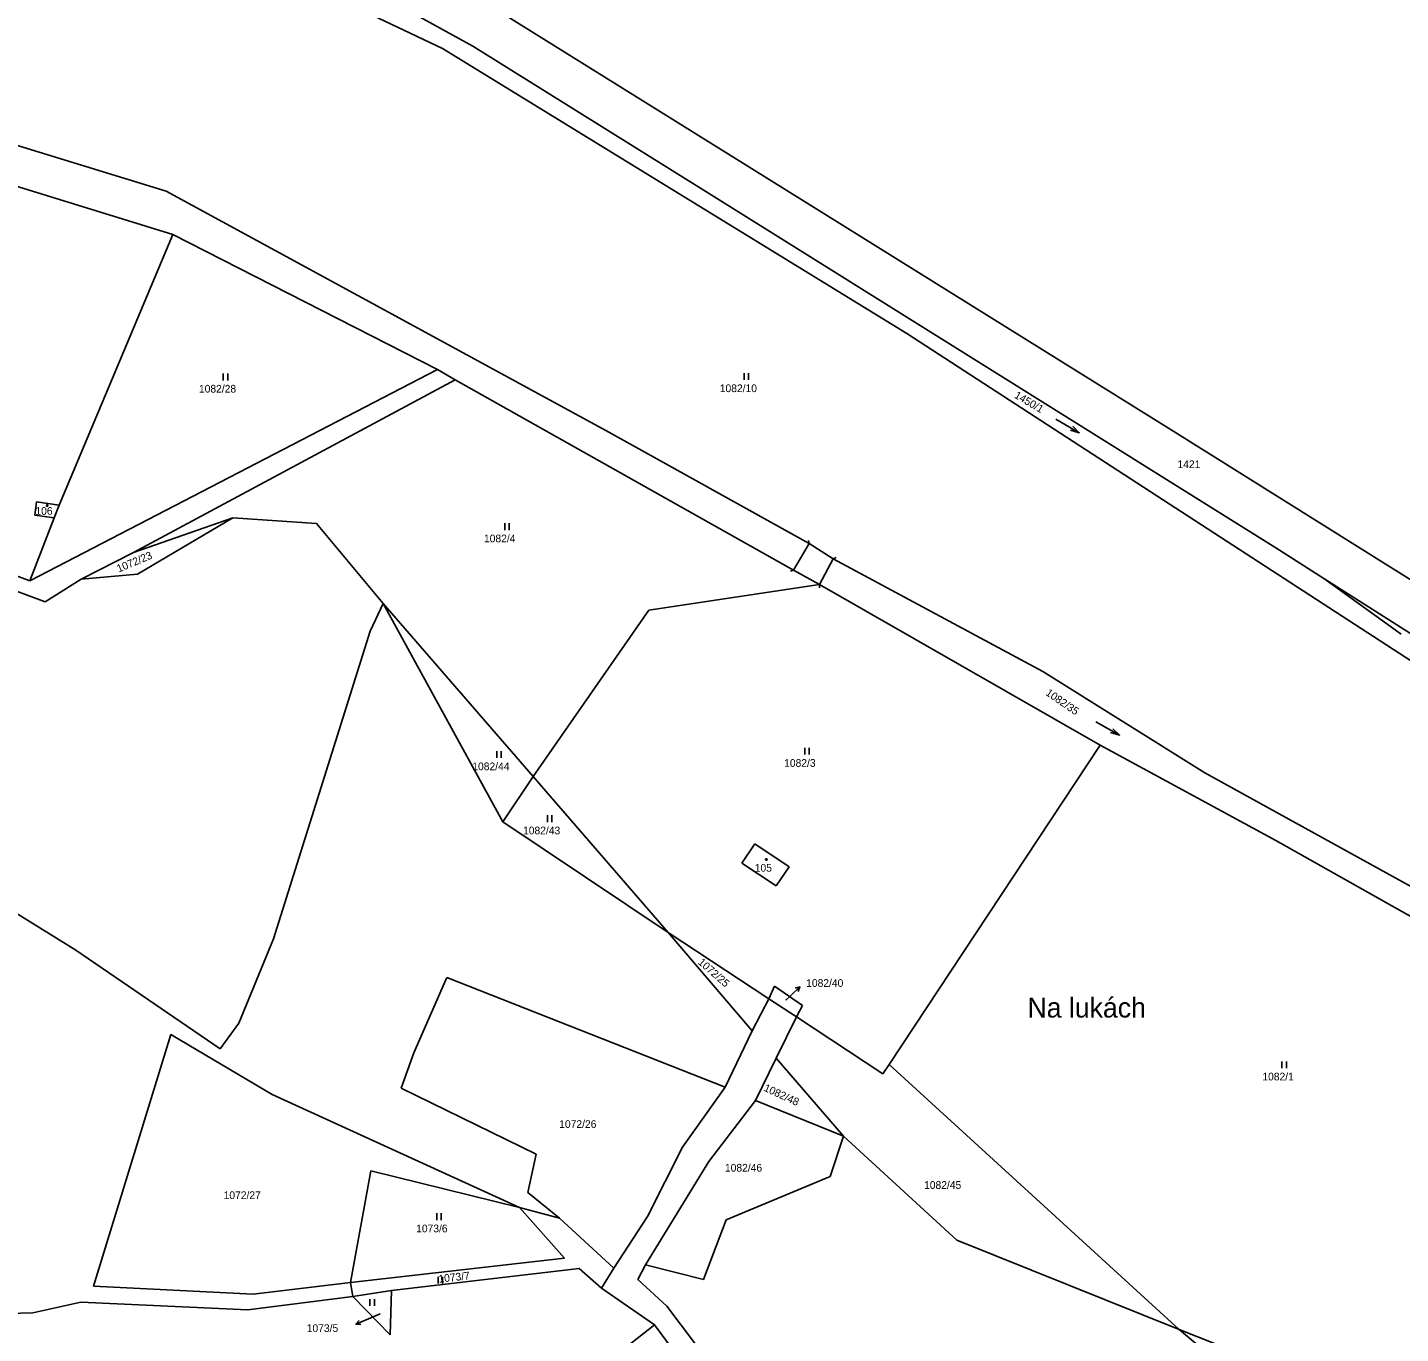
# Model space of a CAD drawing. Extents: x -850689 to -847910, y -1058374 to -1054747.
# Drawn here: x -849820.3 to -849516.8, y -1056154.2 to -1055865.6 of the extents above; entities that cross this region are included whole.
import ezdxf

# ---------------------------------------------------------------- set-up
doc = ezdxf.new("R2010")
doc.units = 0
for name, color, linetype in [('KN_HRANICE', 7, 'Continuous'), ('KN_KULTURY', 7, 'Continuous'), ('KN_PARCELY', 7, 'Continuous'), ('KN_SLUCKY', 7, 'Continuous'), ('KN_STAVEBNI', 7, 'Continuous')]:
    doc.layers.add(name, color=color, linetype=linetype)

# ---------------------------------------------------------------- blocks, each defined once
blk = doc.blocks.new('306')
for p, q in [((-0.5, 1.5), (-0.5, 0)), ((0.5, 0), (0.5, 1.5))]:
    blk.add_line(p, q)
blk = doc.blocks.new('802')
blk.add_line((-3, 0), (3, 0))
blk.add_lwpolyline([(1, 0.5), (3, 0), (1, -0.5)])
blk = doc.blocks.new('10292')
blk.add_line((0, 3), (0, 0))
blk.add_lwpolyline([(-0.5, 2), (0, 3), (0.5, 2)])
blk = doc.blocks.new('4201')
blk.add_line((0, 0), (-0.5, -0.5))
blk = doc.blocks.new('402')
blk.add_lwpolyline([(0.09, 0.15), (0.18, 0), (0.09, -0.15), (-0.09, -0.15), (-0.18, 0), (-0.09, 0.15), (0.09, 0.15)])

msp = doc.modelspace()

# ---------------------------------------------------------------- linework, layer by layer
at = {"layer": 'KN_HRANICE'}
for p, q in [((-849925.48, -1055776.91), (-849728.57, -1055870.26)), ((-849789.66, -1055901.84), (-849941.49, -1055855.07)), ((-849750.81, -1055853.82), (-849721.84, -1055869.75)), ((-849723.4, -1055857.46), (-849567.55, -1055954.51)), ((-849925.74, -1055868.85), (-849788.17, -1055911.4)), ((-849728.57, -1055870.26), (-849625.96, -1055933.24)), ((-849721.84, -1055869.75), (-849670.35, -1055901.85)), ((-849789.66, -1055901.84), (-849692.46, -1055954.72)), ((-849670.35, -1055901.85), (-849544.39, -1055980.59)), ((-849788.17, -1055911.4), (-849813.32, -1055971.18)), ((-849788.17, -1055911.4), (-849729.7, -1055941.2)), ((-849625.96, -1055933.24), (-849531.18, -1055994.73)), ((-849953.34, -1055938.37), (-849819.81, -1055987.92)), ((-849819.81, -1055987.92), (-849729.7, -1055941.2)), ((-849725.75, -1055943.47), (-849729.7, -1055941.2)), ((-849796.89, -1055981.61), (-849725.75, -1055943.47)), ((-849725.75, -1055943.47), (-849651, -1055985.57)), ((-849816.4, -1055992.51), (-849916.66, -1055955.41)), ((-849692.46, -1055954.72), (-849647.54, -1055979.67)), ((-849567.55, -1055954.51), (-849412.04, -1056051.96)), ((-849818.29, -1055970.47), (-849818.7, -1055973.39)), ((-849818.29, -1055970.47), (-849813.32, -1055971.18)), ((-849814.41, -1055974), (-849813.32, -1055971.18)), ((-849819.81, -1055987.92), (-849814.41, -1055974)), ((-849818.7, -1055973.39), (-849814.41, -1055974)), ((-849796.89, -1055981.61), (-849774.92, -1055974.01)), ((-849774.92, -1055974.01), (-849796, -1055986.42)), ((-849756.41, -1055975.27), (-849774.92, -1055974.01)), ((-849741.66, -1055992.91), (-849756.41, -1055975.27)), ((-849647.54, -1055979.67), (-849642.19, -1055983.02)), ((-849544.39, -1055980.59), (-849533.77, -1055987.36)), ((-849808.42, -1055987.54), (-849796.89, -1055981.61)), ((-849642.19, -1055983.02), (-849595.86, -1056007.92)), ((-849796, -1055986.42), (-849808.42, -1055987.54)), ((-849645.25, -1055988.73), (-849651, -1055985.57)), ((-849808.42, -1055987.54), (-849816.4, -1055992.51)), ((-849682.98, -1055994.38), (-849645.25, -1055988.73)), ((-849645.25, -1055988.73), (-849583.23, -1056024.23)), ((-849533.77, -1055987.36), (-849447.97, -1056042.09)), ((-849533.77, -1055987.36), (-849516.66, -1055999.69)), ((-849744.55, -1055999.02), (-849741.66, -1055992.91)), ((-849741.66, -1055992.91), (-849715.21, -1056041.18)), ((-849741.66, -1055992.91), (-849708.56, -1056031.12)), ((-849708.56, -1056031.12), (-849682.98, -1055994.38)), ((-849473.77, -1056032.19), (-849531.18, -1055994.73)), ((-849765.92, -1056066.99), (-849744.55, -1055999.02)), ((-849560.1, -1056030.34), (-849595.86, -1056007.92)), ((-849629.86, -1056094.78), (-849583.23, -1056024.23)), ((-849583.23, -1056024.23), (-849544.37, -1056045.31)), ((-849715.21, -1056041.18), (-849708.56, -1056031.12)), ((-849708.56, -1056031.12), (-849705.72, -1056034.36)), ((-849443.99, -1056094.41), (-849560.1, -1056030.34)), ((-849705.72, -1056034.36), (-849678.66, -1056065.64)), ((-849678.66, -1056065.64), (-849715.21, -1056041.18)), ((-849662.41, -1056050.28), (-849659.57, -1056046.02)), ((-849659.57, -1056046.02), (-849651.93, -1056051.1)), ((-849544.37, -1056045.31), (-849445.63, -1056100.85)), ((-849654.82, -1056055.3), (-849662.41, -1056050.28)), ((-849838.15, -1056051.85), (-849809.64, -1056069.48)), ((-849651.93, -1056051.1), (-849654.82, -1056055.3)), ((-849660.09, -1056087.3), (-849678.66, -1056065.64)), ((-849656.44, -1056080.25), (-849678.66, -1056065.64)), ((-849773.59, -1056085.64), (-849765.92, -1056066.99)), ((-849809.64, -1056069.48), (-849777.71, -1056091.31)), ((-849734.87, -1056092.19), (-849727.59, -1056075.54)), ((-849727.59, -1056075.54), (-849666.07, -1056099.8)), ((-849655.22, -1056077.44), (-849656.44, -1056080.25)), ((-849649.02, -1056081.72), (-849655.22, -1056077.44)), ((-849660.09, -1056087.3), (-849656.44, -1056080.25)), ((-849650.34, -1056084.27), (-849656.44, -1056080.25)), ((-849650.34, -1056084.27), (-849649.02, -1056081.72)), ((-849777.71, -1056091.31), (-849773.59, -1056085.64)), ((-849654.81, -1056093.4), (-849650.34, -1056084.27)), ((-849631.22, -1056096.84), (-849650.34, -1056084.27)), ((-849788.62, -1056088.16), (-849805.73, -1056143.74)), ((-849766.22, -1056101.38), (-849788.62, -1056088.16)), ((-849660.09, -1056087.3), (-849666.07, -1056099.8)), ((-849734.87, -1056092.19), (-849737.69, -1056099.99)), ((-849659.37, -1056102.71), (-849654.81, -1056093.4)), ((-849639.94, -1056110.6), (-849654.81, -1056093.4)), ((-849631.22, -1056096.84), (-849629.86, -1056094.78)), ((-849629.86, -1056094.78), (-849565.73, -1056153.32)), ((-849711.58, -1056126.38), (-849766.22, -1056101.38)), ((-849737.69, -1056099.99), (-849707.88, -1056114.62)), ((-849666.07, -1056099.8), (-849675.53, -1056113.02)), ((-849669.71, -1056116.18), (-849659.37, -1056102.71)), ((-849659.37, -1056102.71), (-849639.94, -1056110.6)), ((-849642.89, -1056119.55), (-849639.94, -1056110.6)), ((-849639.94, -1056110.6), (-849614.89, -1056133.59)), ((-849675.53, -1056113.02), (-849683.26, -1056128.33)), ((-849707.88, -1056114.62), (-849709.73, -1056123.05)), ((-849683.7, -1056139.02), (-849669.71, -1056116.18)), ((-849748.92, -1056142.97), (-849744.42, -1056118.28)), ((-849744.42, -1056118.28), (-849711.58, -1056126.38)), ((-849665.85, -1056129.09), (-849642.89, -1056119.55)), ((-849709.73, -1056123.05), (-849702.72, -1056128.75)), ((-849711.58, -1056126.38), (-849702.72, -1056128.75)), ((-849701.62, -1056137.6), (-849711.58, -1056126.38)), ((-849690.71, -1056139.77), (-849702.72, -1056128.75)), ((-849683.26, -1056128.33), (-849690.71, -1056139.77)), ((-849670.9, -1056142.31), (-849665.85, -1056129.09)), ((-849614.89, -1056133.59), (-849565.73, -1056153.32)), ((-849748.92, -1056142.97), (-849701.62, -1056137.6)), ((-849739.81, -1056144.71), (-849698.33, -1056139.88)), ((-849698.33, -1056139.88), (-849693.42, -1056144.17)), ((-849690.71, -1056139.77), (-849693.42, -1056144.17)), ((-849683.7, -1056139.02), (-849685.43, -1056142.27)), ((-849683.7, -1056139.02), (-849670.9, -1056142.31)), ((-849805.73, -1056143.74), (-849770.42, -1056145.53)), ((-849770.42, -1056145.53), (-849748.92, -1056142.97)), ((-849748.39, -1056146.04), (-849748.92, -1056142.97)), ((-849693.42, -1056144.17), (-849681.71, -1056152.3)), ((-849685.43, -1056142.27), (-849679.02, -1056148.18)), ((-849819.12, -1056149.64), (-849808.52, -1056147.27)), ((-849808.52, -1056147.27), (-849771.61, -1056149)), ((-849771.61, -1056149), (-849748.39, -1056146.04)), ((-849748.39, -1056146.04), (-849739.81, -1056144.71)), ((-849748.39, -1056146.04), (-849740.13, -1056154.54)), ((-849739.81, -1056144.71), (-849740.13, -1056154.54)), ((-849837.94, -1056150.19), (-849819.12, -1056149.64)), ((-849679.02, -1056148.18), (-849647.93, -1056189.13)), ((-849681.71, -1056152.3), (-849708.52, -1056173.28)), ((-849681.71, -1056152.3), (-849647.07, -1056198.84)), ((-849565.73, -1056153.32), (-849533.49, -1056180.31)), ((-849565.73, -1056153.32), (-849527.38, -1056168.45))]:
    msp.add_line(p, q, dxfattribs=at)
at = {"layer": 'KN_PARCELY'}
for p, q in [((-849652.7, -1056080.56), (-849651.76, -1056079.68)), ((-849742.32, -1056149.85), (-849744.95, -1056150.99))]:
    msp.add_line(p, q, dxfattribs=at)
at = {"layer": 'KN_SLUCKY'}
for p, q in [((-849651, -1055985.57), (-849647.54, -1055979.67)), ((-849642.19, -1055983.02), (-849645.25, -1055988.73))]:
    msp.add_line(p, q, dxfattribs=at)
at = {"layer": 'KN_STAVEBNI'}
for p, q in [((-849818.29, -1055970.47), (-849818.7, -1055973.39)), ((-849818.29, -1055970.47), (-849813.32, -1055971.18)), ((-849814.41, -1055974), (-849813.32, -1055971.18)), ((-849818.7, -1055973.39), (-849814.41, -1055974)), ((-849662.41, -1056050.28), (-849659.57, -1056046.02)), ((-849659.57, -1056046.02), (-849651.93, -1056051.1)), ((-849654.82, -1056055.3), (-849662.41, -1056050.28)), ((-849651.93, -1056051.1), (-849654.82, -1056055.3))]:
    msp.add_line(p, q, dxfattribs=at)

# ---------------------------------------------------------------- block references
at = {"layer": 'KN_KULTURY'}
for name, p in [('306', (-849776.53, -1055943.61)), ('306', (-849661.41, -1055943.51)), ('402', (-849815.94, -1055971.28)), ('306', (-849714.3, -1055976.7)), ('306', (-849716.07, -1056027.05)), ('306', (-849648, -1056026.3)), ('306', (-849704.89, -1056041.22)), ('402', (-849657, -1056049.47)), ('306', (-849542.54, -1056095.59)), ('306', (-849729.33, -1056129.15)), ('306', (-849729.06, -1056143.18)), ('306', (-849744.11, -1056148.11))]:
    msp.add_blockref(name, p, dxfattribs=at)
for p, rotation in [((-849590.4, -1055953.67), -30.434675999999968), ((-849581.52, -1056020.52), -29.346056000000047)]:
    msp.add_blockref('802', p, dxfattribs=dict(at, rotation=rotation))
at = {"layer": 'KN_PARCELY'}
for p, rotation in [((-849651.76, -1056079.68), -46.706677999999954), ((-849744.95, -1056150.99), 113.38834800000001)]:
    msp.add_blockref('10292', p, dxfattribs=dict(at, rotation=rotation))
at = {"layer": 'KN_SLUCKY'}
for p, rotation in [((-849647.54, -1055979.67), -124.22786700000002), ((-849642.19, -1055983.02), 155.27156200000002), ((-849651, -1055985.57), -27.799070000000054), ((-849645.25, -1055988.73), 47.670089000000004)]:
    msp.add_blockref('4201', p, dxfattribs=dict(at, rotation=rotation))

# ---------------------------------------------------------------- texts
at = {"layer": 'KN_PARCELY'}
for s, height, p in [('1082/28', 1.7, (-849782.4, -1055946.31)), ('1082/10', 1.7, (-849667.28, -1055946.21)), ('1421', 1.7, (-849566.12, -1055963)), ('106', 1.7, (-849818.54, -1055973.31)), ('1082/4', 1.7, (-849719.4, -1055979.4)), ('1082/44', 1.7, (-849721.98, -1056029.75)), ('1082/3', 1.7, (-849653.06, -1056029)), ('1082/43', 1.7, (-849710.76, -1056043.92)), ('105', 1.7, (-849659.55, -1056052.17)), ('1082/40', 1.7, (-849648.19, -1056077.62)), ('1082/40', 0.1, (-849653.05, -1056080.56)), ('Na lukách', 4.4, (-849599.27, -1056084.4)), ('1082/1', 1.7, (-849547.36, -1056098.29)), ('1072/26', 1.7, (-849702.77, -1056108.79)), ('1082/46', 1.7, (-849666.14, -1056118.44)), ('1072/27', 1.7, (-849776.94, -1056124.5)), ('1082/45', 1.7, (-849622.13, -1056122.25)), ('1073/6', 1.7, (-849734.39, -1056131.85)), ('1073/5', 0.1, (-849742.62, -1056149.85)), ('1073/5', 1.7, (-849758.57, -1056153.88))]:
    msp.add_text(s, height=height, dxfattribs=at).set_placement(p)
for s, rotation, p in [('1450/1', 329.508, (-849602.34, -1055947.35)), ('1072/23', 22.746, (-849800.14, -1055986.08)), ('1082/35', 325.44, (-849595.41, -1056013.02)), ('1072/25', 318.565, (-849672.23, -1056072.39)), ('1082/48', 335.18, (-849657.71, -1056100.52)), ('1073/7', 6.36, (-849729.37, -1056143))]:
    msp.add_text(s, height=1.7, rotation=rotation, dxfattribs=at).set_placement(p)

doc.saveas('drawing.dxf')
